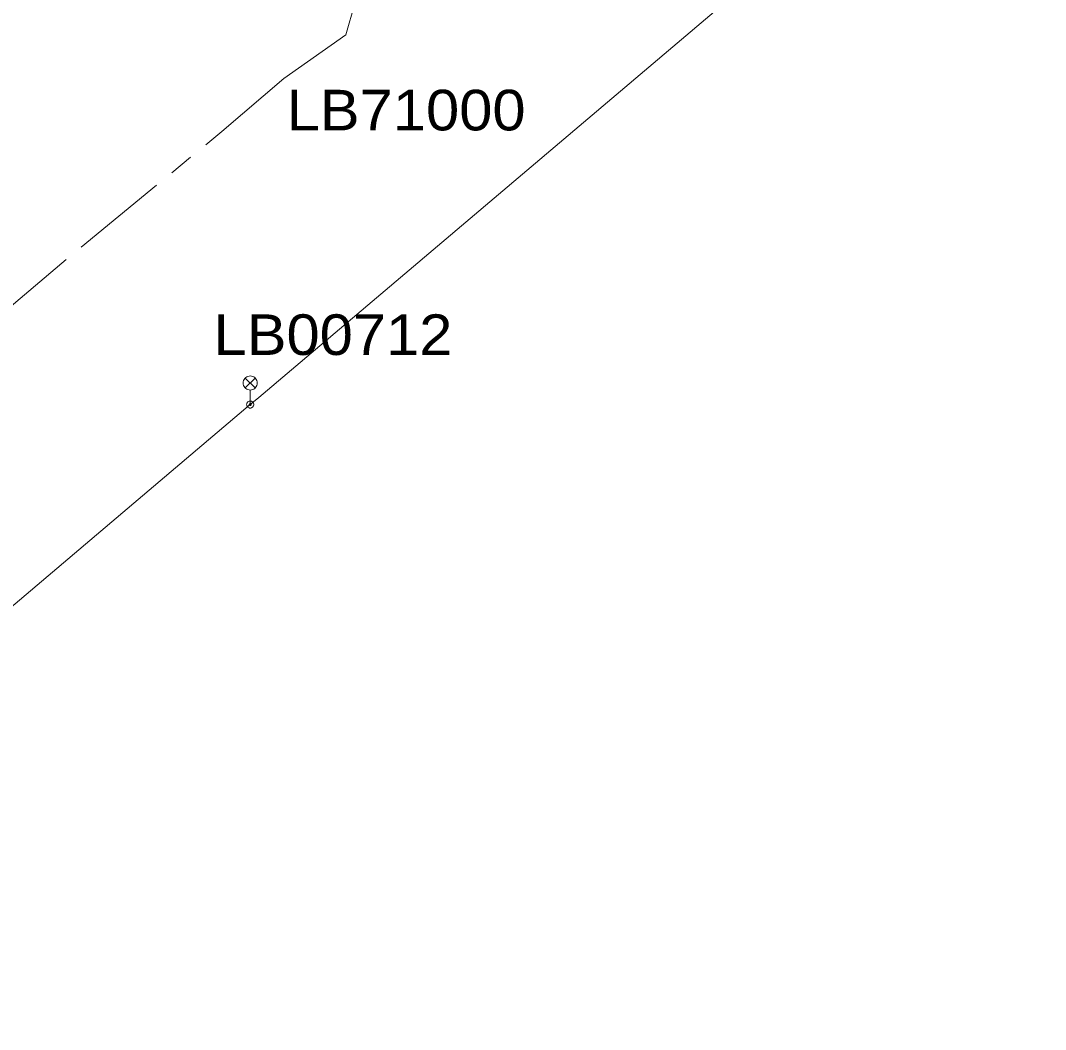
# Model space of a CAD drawing. Extents: x -688049 to -687261, y -973611 to -973038.
# Drawn here: x -687811.1 to -687756.4, y -973178.7 to -973124.8 of the extents above; entities that cross this region are included whole.
import ezdxf

# ---------------------------------------------------------------- set-up
doc = ezdxf.new("R2010")
doc.units = 0
doc.header["$LTSCALE"] = 0.87
doc.linetypes.add('LONG_DASH_SHORT_DASH', pattern=[9.9, 6, -1.2, 1.5, -1.2])
doc.layers.add('1', color=7, linetype='Continuous', lineweight=13)

msp = doc.modelspace()

# ---------------------------------------------------------------- linework, layer by layer
at = {"layer": '1'}
for p, q in [((-687799.125, -973143.925), (-687798.595, -973144.455)), ((-687799.125, -973144.455), (-687798.595, -973143.925)), ((-687798.86, -973145.34), (-687798.86, -973144.565))]:
    msp.add_line(p, q, dxfattribs=at)
for points in [[(-687756.36, -973109.66), (-687756.954, -973109.852), (-687798.405, -973144.971), (-687798.86, -973145.34)], [(-687797.06, -973127.92), (-687797.06, -973127.92), (-687793.746, -973125.582), (-687793.273, -973123.922), (-687786.073, -973117.922), (-687783.63, -973117.93)], [(-687798.86, -973145.34), (-687837.965, -973178.484), (-687838.52, -973178.73)]]:
    msp.add_lwpolyline(points, dxfattribs=at)
at = {"layer": '1', "linetype": 'LONG_DASH_SHORT_DASH'}
msp.add_lwpolyline([(-687828.14, -973154.08), (-687819.26, -973146.52), (-687807.9, -973136.93), (-687800.37, -973130.76), (-687797.06, -973127.92)], dxfattribs=at)
at = {"layer": '1'}
for points in [[(-687798.485, -973144.19), (-687798.491, -973144.125), (-687798.508, -973144.062), (-687798.535, -973144.003), (-687798.573, -973143.949), (-687798.619, -973143.903), (-687798.672, -973143.865), (-687798.732, -973143.838), (-687798.795, -973143.821), (-687798.86, -973143.815), (-687798.925, -973143.821), (-687798.988, -973143.838), (-687799.048, -973143.865), (-687799.101, -973143.903), (-687799.147, -973143.949), (-687799.185, -973144.003), (-687799.212, -973144.062), (-687799.229, -973144.125), (-687799.235, -973144.19), (-687799.229, -973144.255), (-687799.212, -973144.318), (-687799.185, -973144.378), (-687799.147, -973144.431), (-687799.101, -973144.477), (-687799.048, -973144.515), (-687798.988, -973144.542), (-687798.925, -973144.559), (-687798.86, -973144.565), (-687798.795, -973144.559), (-687798.732, -973144.542), (-687798.672, -973144.515), (-687798.619, -973144.477), (-687798.573, -973144.431), (-687798.535, -973144.378), (-687798.508, -973144.318), (-687798.491, -973144.255)], [(-687798.67, -973145.34), (-687798.673, -973145.307), (-687798.681, -973145.275), (-687798.695, -973145.245), (-687798.714, -973145.218), (-687798.738, -973145.194), (-687798.765, -973145.175), (-687798.795, -973145.161), (-687798.827, -973145.153), (-687798.86, -973145.15), (-687798.893, -973145.153), (-687798.925, -973145.161), (-687798.955, -973145.175), (-687798.982, -973145.194), (-687799.006, -973145.218), (-687799.025, -973145.245), (-687799.039, -973145.275), (-687799.047, -973145.307), (-687799.05, -973145.34), (-687799.047, -973145.373), (-687799.039, -973145.405), (-687799.025, -973145.435), (-687799.006, -973145.462), (-687798.982, -973145.486), (-687798.955, -973145.505), (-687798.925, -973145.519), (-687798.893, -973145.527), (-687798.86, -973145.53), (-687798.827, -973145.527), (-687798.795, -973145.519), (-687798.765, -973145.505), (-687798.738, -973145.486), (-687798.714, -973145.462), (-687798.695, -973145.435), (-687798.681, -973145.405), (-687798.673, -973145.373)], [(-687798.81, -973145.34), (-687798.811, -973145.331), (-687798.813, -973145.323), (-687798.817, -973145.315), (-687798.822, -973145.308), (-687798.828, -973145.302), (-687798.835, -973145.297), (-687798.843, -973145.293), (-687798.851, -973145.291), (-687798.86, -973145.29), (-687798.869, -973145.291), (-687798.877, -973145.293), (-687798.885, -973145.297), (-687798.892, -973145.302), (-687798.898, -973145.308), (-687798.903, -973145.315), (-687798.907, -973145.323), (-687798.909, -973145.331), (-687798.91, -973145.34), (-687798.909, -973145.349), (-687798.907, -973145.357), (-687798.903, -973145.365), (-687798.898, -973145.372), (-687798.892, -973145.378), (-687798.885, -973145.383), (-687798.877, -973145.387), (-687798.869, -973145.389), (-687798.86, -973145.39), (-687798.851, -973145.389), (-687798.843, -973145.387), (-687798.835, -973145.383), (-687798.828, -973145.378), (-687798.822, -973145.372), (-687798.817, -973145.365), (-687798.813, -973145.357), (-687798.811, -973145.349)]]:
    msp.add_lwpolyline(points, close=True, dxfattribs=at)

# ---------------------------------------------------------------- texts
at = {"layer": '1', "width": 1.1}
for s, height, p in [('LB71000', 2.168, (-687796.913, -973130.693)), ('LB00712', 2.167, (-687800.82, -973142.691))]:
    msp.add_text(s, height=height, dxfattribs=at).set_placement(p)

doc.saveas('drawing.dxf')
